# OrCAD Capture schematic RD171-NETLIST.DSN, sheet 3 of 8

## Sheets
3 6: size A3
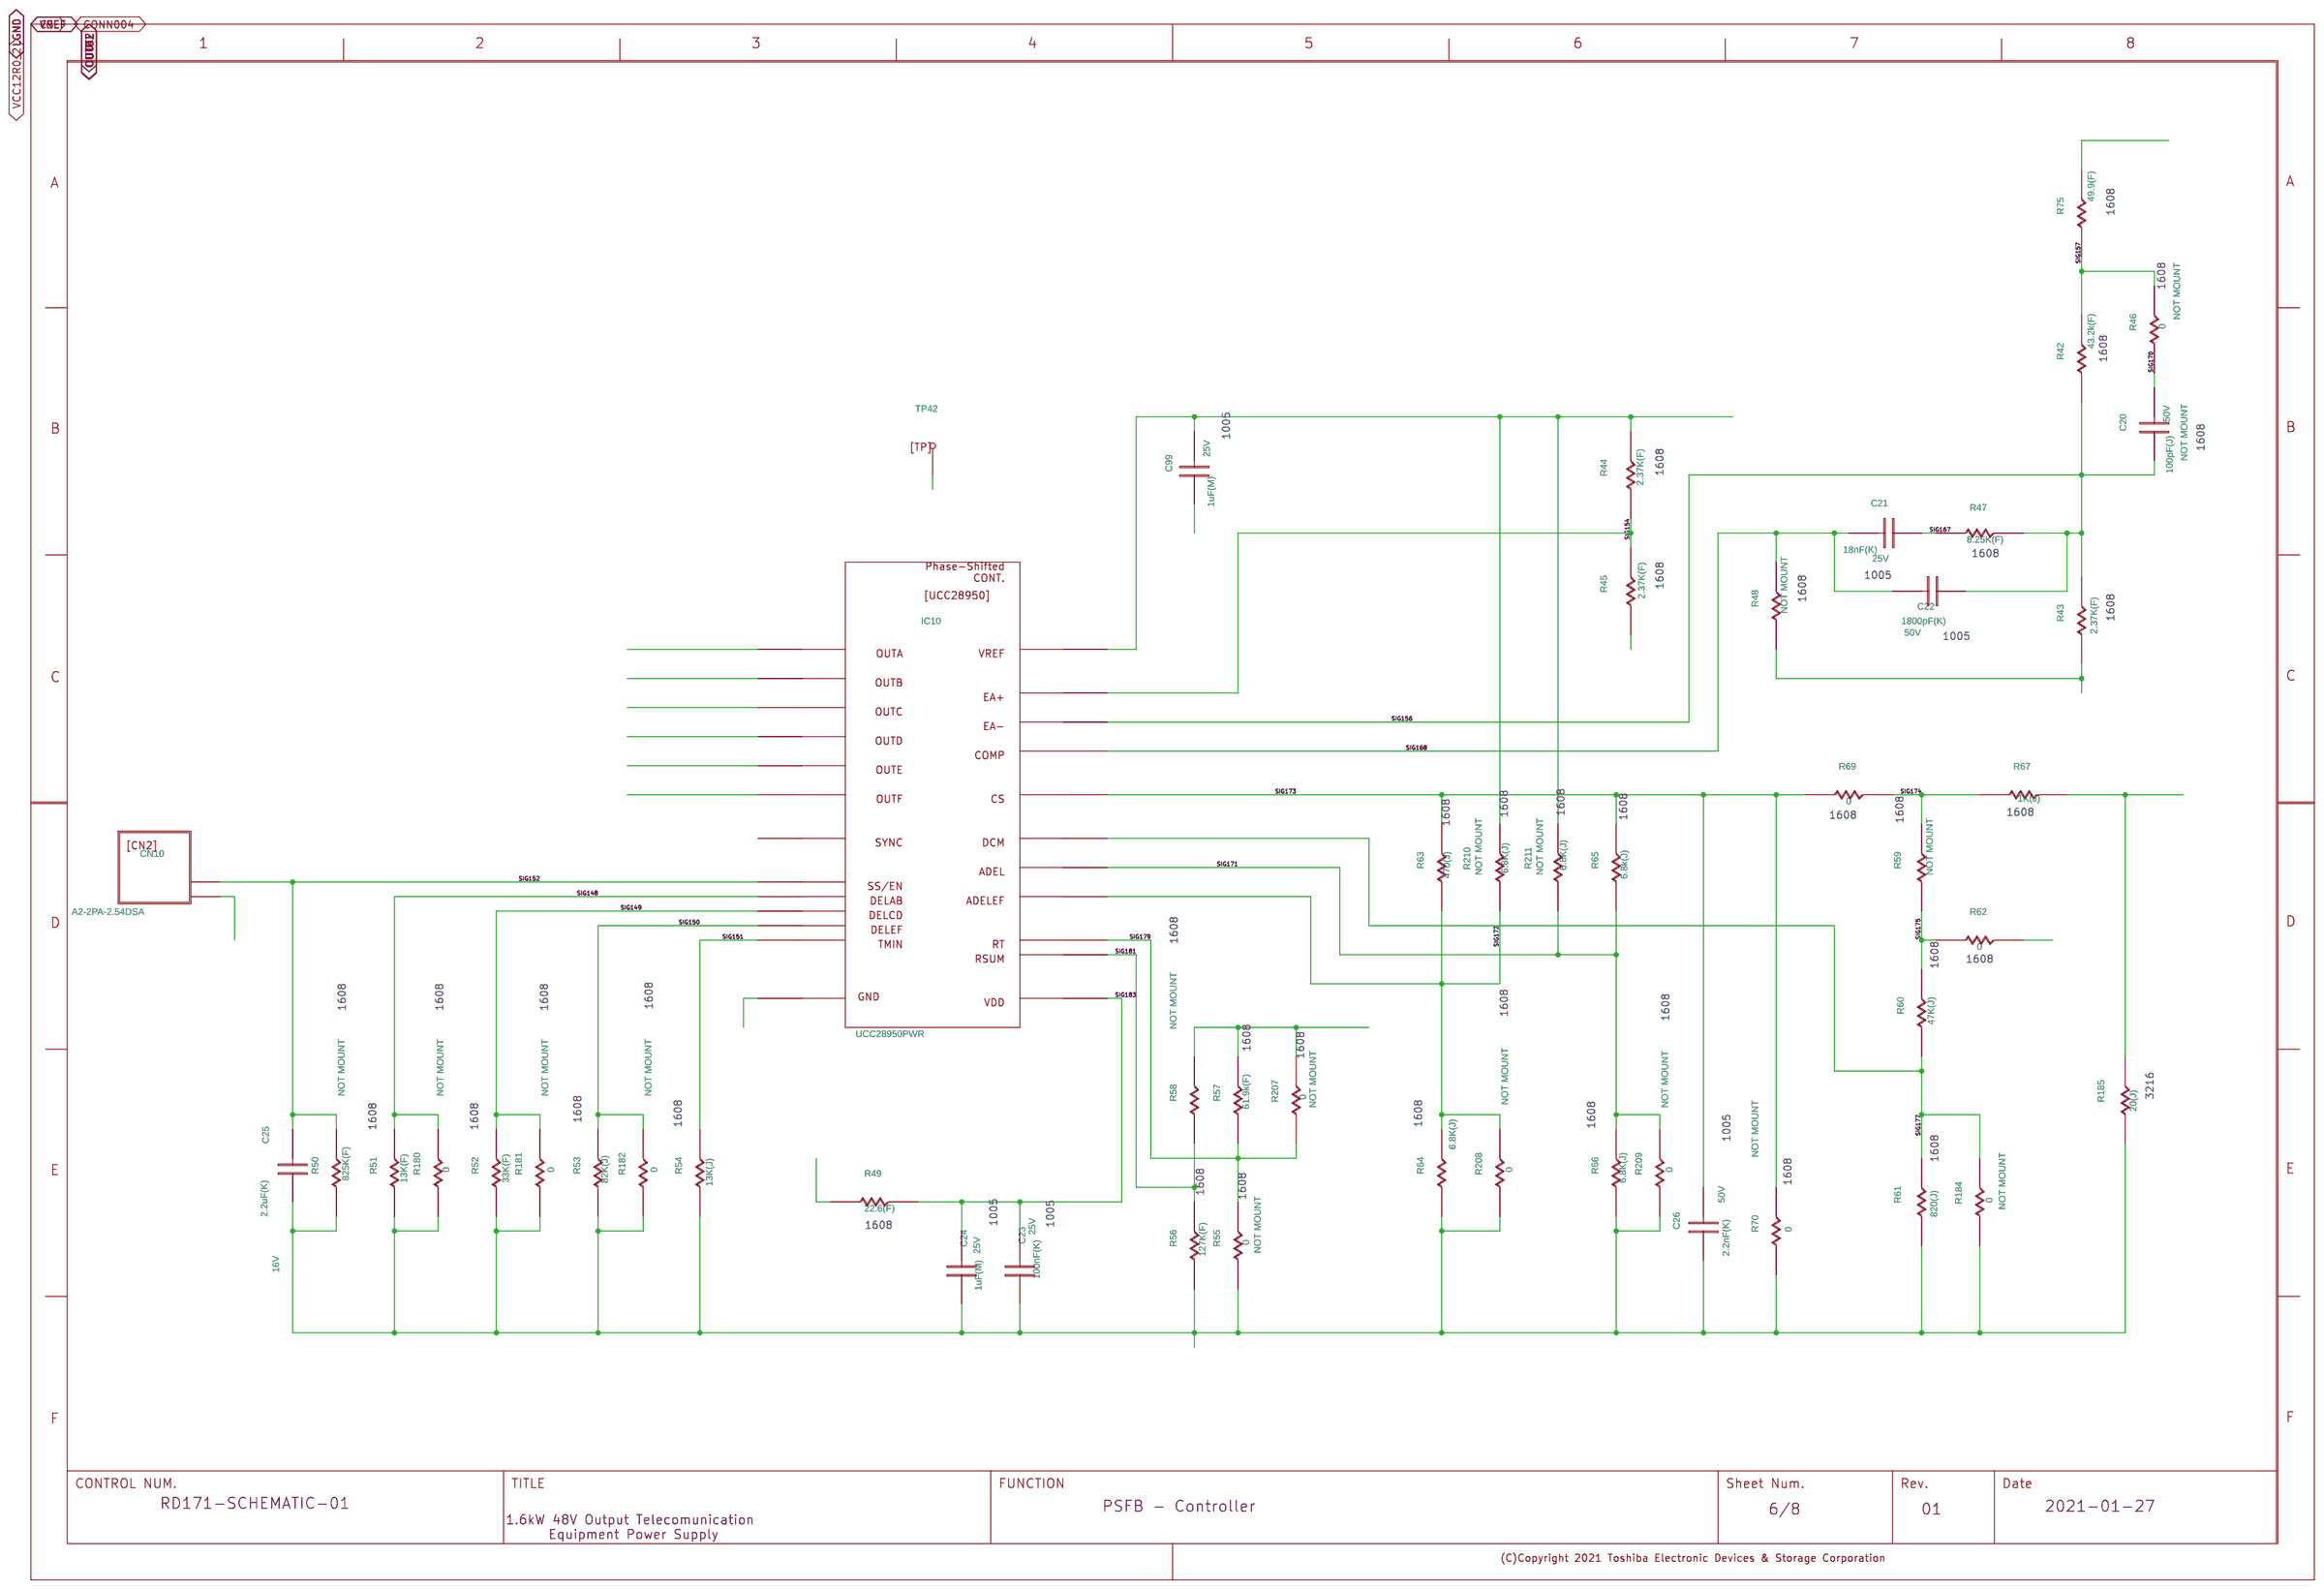
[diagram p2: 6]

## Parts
C20  100pF
C21  18nF
C22  1800pF
C23  100nF
C24  1uF
C25  2.2uF
C26  2.2nF
C99  1uF
CN10  CN10  [A2-2PA-2.54DSA]
IC10  IC10  [UCC28950PWR]
R42  43.2k  [RN73H1JTTD4322F25]
R43  2.37k
R44  2.37k
R45  2.37k
R46  0
R47  8.25k
R48  0
R49  22.6
R50  825k
R51  13k
R52  33k
R53  100k
R54  13k
R55  0
R56  127k
R57  61.9k  [RN73H1JTTD6192F50]
R58  0
R59  0
R60  47k
R61  820
R62  0
R63  100
R64  6.8k
R65  6.8k
R66  6.8k
R67  1k
R69  0
R70  0
R75  49.9
R180  0
R181  0
R182  0
R184  0
R185  20
R207  0
R208  0
R209  0
R210  6.8k
R211  6.8k
TP42  TP42  [LC-22-S-BLACK]
U?#2  WAKU_DEF100

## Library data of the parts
C20 = C: ADSMODELNAME: s_GRM188B11E104KA01D; CAPACITANCETOLE: K; CDMASTERCADCELG: KC0008; CHIPSIZE: 1608; COMP: PRT_48; COMPONENTNAME: C_C.Normal_package; FNLEADFREETHET1GT2GMCTH1: 3_1_N; FUNCTION: C_C.Normal_package; GCOUNT: 1; INSTANCENAME: INS8954; MAXGCOUNT: 1; NOMINALCAPACITA: 100n; NOTMOUNT: NOT MOUNT; OUMECLASSIFICATION: ƒZƒ‰ƒ~ƒbƒNƒRƒ“ƒfƒ“ƒT; OUMEMAKER: MRT ºc»ì; OUMEMAKERKATAMEI: GRM188B11E104KA01D; PARTNAME: Chip1608_GS_1; PMPRODUCTSTYPEG: PC1; QUADMODEL: CON_100N; RATEDVOLTAGE: 25; SIZECODESMD: 1608; TEMPCHARACTERI2: B; VAL1: 100pF(J); VAL2: 50V; VAL3: GRM1885C1H101JA01D
C21 = C: ADSCNVFLAG: ON; ADSCOMPONENTNAME: C_1005; ADSMODELNAME: s_GRM155B11E562KA01D; CAPACITANCETOLE: K; CDMASTERCADCELG: KC0005; CHIPSIZE: 1005; COMP: PRT_52; COMPONENTNAME: C_C.Normal_package; FNLEADFREETHET1GT2GMCTH1: 2_0_N; FUNCTION: C_C.Normal_package; GCOUNT: 1; ICX_PART_MODEL: CON_5.6N; INSTANCENAME: INS8656; MAKER: MURATA; MAXGCOUNT: 1; NOMINALCAPACITA: 5.6n; OUMECLASSIFICATION: ƒZƒ‰ƒ~ƒbƒNƒRƒ“ƒfƒ“ƒT; OUMEMAKER: MRT ºc»ì; OUMEMAKERKATAMEI: GRM155B11E562KA01D; PARTNAME: Chip1005_GS_2; PMPRODUCTSTYPEG: HD1; QUADMODEL: CON_5.6N; RATEDVOLTAGE: 25; SIZECODESMD: 1005; SQ_PART_MODEL: CON_5.6N; TEMPCHARACTERI2: B; VAL1: 18nF(K); VAL2: 25V; VAL3: GRM155R71E183KA61D
C22 = C: ADSCNVFLAG: ON; ADSCOMPONENTNAME: C_1005; ADSMODELNAME: s_C1005JB1H561KT; CAPACITANCETOLE: K; CDMASTERCADCELG: KC0005; CHIPSIZE: 1005; COMP: PRT_52; COMPONENTNAME: C_C.Normal_package; FNLEADFREETHET1GT2GMCTH1: 2_0_N; FUNCTION: C_C.Normal_package; GCOUNT: 1; ICX_PART_MODEL: CON_560P; INSTANCENAME: INS8666; MAKER: MURATA; MAXGCOUNT: 1; NOMINALCAPACITA: 560p; OUMECLASSIFICATION: ƒZƒ‰ƒ~ƒbƒNƒRƒ“ƒfƒ“ƒT; OUMEMAKER: TDK ‚s‚c‚j; OUMEMAKERKATAMEI: C1005JB1H561KT; PARTNAME: Chip1005_GS_2; PMPRODUCTSTYPEG: HD1-PC1; QUADMODEL: CON_560P; RATEDVOLTAGE: 50; SIZECODESMD: 1005; SQ_PART_MODEL: CON_560P; TEMPCHARACTERI2: B; VAL1: 1800pF(K); VAL2: 50V; VAL3: GRM155R71H182KA01D
C23 = C: ADSMODELNAME: s_GRM155R71E104KE14D; CAPACITANCETOLE: K; CDMASTERCADCELG: KC0005; CHIPSIZE: 1005; COMP: PRT_52; COMPONENTNAME: C_C.Normal_package; FNLEADFREETHET1GT2GMCTH1: N_N_N; FUNCTION: C_C.Normal_package; GCOUNT: 1; INSTANCENAME: INS8708; MAKER: TDK; MAXGCOUNT: 1; NOMINALCAPACITA: 100n; OUMECLASSIFICATION: ƒZƒ‰ƒ~ƒbƒNƒRƒ“ƒfƒ“ƒT; OUMEMAKER: MRT ºc»ì; OUMEMAKERKATAMEI: GRM155R71E104KE14D; PARTNAME: Chip1005_GS_2; QUADMODEL: CON_100N; RATEDVOLTAGE: 25; SIZECODESMD: 1005; VAL1: 100nF(K); VAL2: 25V; VAL3: C1005X7R1E104K050BB
C24 = C: ADSMODELNAME: s_GRM155B31E105KA12D; CAPACITANCETOLE: K; CDMASTERCADCELG: KC0005; CHIPSIZE: 1005; COMP: PRT_52; COMPONENTNAME: C_C.Normal_package; FNLEADFREETHET1GT2GMCTH1: 3_0_N; FUNCTION: C_C.Normal_package; GCOUNT: 1; INSTANCENAME: INS8718; MAKER: TDK; MAXGCOUNT: 1; NOMINALCAPACITA: 1u; OUMECLASSIFICATION: ƒZƒ‰ƒ~ƒbƒNƒRƒ“ƒfƒ“ƒT; OUMEMAKER: MRT ºc»ì; OUMEMAKERKATAMEI: GRM155B31E105KA12D; PARTNAME: Chip1005_GS_2; PMPRODUCTSTYPEG: HD1; QUADMODEL: CON_1U; RATEDVOLTAGE: 25; SIZECODESMD: 1005; TEMPCHARACTERI2: B; VAL1: 1uF(M); VAL2: 25V; VAL3: C1005X5R1E105M050BC
C25 = C: ADSMODELNAME: s_GRM155C81C225KE11; CAPACITANCETOLE: K; CDMASTERCADCELG: KC0005; CHIPSIZE: 1005; COMP: PRT_52; COMPONENTNAME: C_C.Normal_package; FNLEADFREETHET1GT2GMCTH1: 3_0_N; FUNCTION: C_C.Normal_package; GCOUNT: 1; INSTANCENAME: INS8624; MAKER: MURATA; MAXGCOUNT: 1; NOMINALCAPACITA: 150n; OUMECLASSIFICATION: ƒZƒ‰ƒ~ƒbƒNƒRƒ“ƒfƒ“ƒT; OUMEMAKER: MURATA; OUMEMAKERKATAMEI: GRM155C81C225KE11; PARTNAME: Chip1005_GS_2; PMPRODUCTSTYPEG: HD1; RATEDVOLTAGE: 25; SIZECODESMD: 1005; VAL1: 2.2uF(K); VAL2: 16V; VAL3: GRM155C81C225KE11
C26 = C: ADSMODELNAME: s_UMK105BJ222KV_F; CAPACITANCETOLE: K; CDMASTERCADCELG: KC0005; CHIPSIZE: 1005; COMP: PRT_52; COMPONENTNAME: C_C.Normal_package; FNLEADFREETHET1GT2GMCTH1: 2_0_N; FUNCTION: C_C.Normal_package; GCOUNT: 1; INSTANCENAME: INS8762; MAKER: TDK; MAXGCOUNT: 1; NOMINALCAPACITA: 2.2n; OUMECLASSIFICATION: ƒZƒ‰ƒ~ƒbƒNƒRƒ“ƒfƒ“ƒT; OUMEMAKER: TYD ‘¾—z—U“d; OUMEMAKERKATAMEI: UMK105BJ222KV-F; PARTNAME: Chip1005_GS_2; PMPRODUCTSTYPEG: HD1-PC1; QUADMODEL: CON_2.2N; RATEDVOLTAGE: 50; SIZECODESMD: 1005; TEMPCHARACTERI2: B; VAL1: 2.2nF(K); VAL2: 50V; VAL3: UMK105BJ222KV-F
C99 = C: ADSMODELNAME: s_GRM155B31E105KA12D; CAPACITANCETOLE: K; CDMASTERCADCELG: KC0005; CHIPSIZE: 1005; COMP: PRT_52; COMPONENTNAME: C_C.Normal_package; FNLEADFREETHET1GT2GMCTH1: 3_0_N; FUNCTION: C_C.Normal_package; GCOUNT: 1; INSTANCENAME: INS8728; MAKER: TDK; MAXGCOUNT: 1; NOMINALCAPACITA: 1u; OUMECLASSIFICATION: ƒZƒ‰ƒ~ƒbƒNƒRƒ“ƒfƒ“ƒT; OUMEMAKER: MRT ºc»ì; OUMEMAKERKATAMEI: GRM155B31E105KA12D; PARTNAME: Chip1005_GS_2; PMPRODUCTSTYPEG: HD1; QUADMODEL: CON_1U; RATEDVOLTAGE: 25; SIZECODESMD: 1005; TEMPCHARACTERI2: B; VAL1: 1uF(M); VAL2: 25V; VAL3: C1005X5R1E105M050BC
CN10 = CN2: COMP: PRT_56; COMPONENTNAME: CN2_CN2.Normal_package; FUNCTION: CN2_CN2.Normal_package; INSTANCENAME: INS9156; MAKER: HIROSE; PARTNAME: A2-2PA-2.54DSA_HR
IC10 = L28950: COMP: PRT_16; COMPONENTNAME: L28950_L28950.Normal_package; FUNCTION: L28950_L28950.Normal_package; INSTANCENAME: INS8570; MAKER: TEXAS; PARTNAME: UCC28950PWR_GS_1; SAVECOUNT: 1; UPDATEDATE: 2020/07/08; UPDATETIME: 16:40:04
R42 = R: ADSMODELNAME: s_RN73H1JTTD4322F25; CDMASTERCADCELG: KC0008; CHIPSIZE: 1608; COMP: PRT_8; COMPONENTNAME: R_R.Normal_package; FNLEADFREETHET1GT2GMCTH1: N_N_N; FUNCTION: R_R.Normal_package; GCOUNT: 1; INSTANCENAME: INS8646; MAKER: PANASONIC; MAXGCOUNT: 1; MOUNTINGFORMSMD: SMD; NOMINALRESISTAN: 9.09K; OUMECLASSIFICATION: \ÊÀpÅèïRí; OUMEMAKER: KOA R[A; OUMEMAKERKATAMEI: RN73H1JTTD9091B10; PARTNAME: Chip1608_GS_1; PMPRODUCTSTYPEG: DME; POWERRATING: 100m; QUADMODEL: RES_9.09K; RESISTANCETOLER: B; SIZECODESMD: 1608; VAL1: 43.2k(F); VAL2: 100mW,}1%; VAL3: ERJ-3EKF9091V
R43 = R: ADSMODELNAME: s_ERJ3EKF2201V@@; CDMASTERCADCELG: KC0165; CHIPSIZE: 1608; COMP: PRT_8; COMPONENTNAME: R_R.Normal_package; FNLEADFREETHET1GT2GMCTH1: 3_2_N; FUNCTION: R_R.Normal_package; GCOUNT: 1; INSTANCENAME: INS8966; MAKER: PANASONIC; MAXGCOUNT: 1; MOUNTINGFORMSMD: SMD; NOMINALRESISTAN: 2.2K; OUMECLASSIFICATION: \ÊÀpÅèïRí; OUMEMAKER: NAE pi\jbNGNgjbNfoCX; OUMEMAKERKATAMEI: ERJ3EKF2201V@@; PARTNAME: Chip1608_GS_1; PMPRODUCTSTYPEG: DA; POWERRATING: 100m; QUADMODEL: RES_2.2K; RESISTANCETOLER: F; SIZECODESMD: 1608; VAL1: 2.37K(F); VAL2: 100mW,}1%; VAL3: ERJ-3EKF2371V
R44 = R: ADSMODELNAME: s_ERJ3EKF2201V@@; CDMASTERCADCELG: KC0165; CHIPSIZE: 1608; COMP: PRT_8; COMPONENTNAME: R_R.Normal_package; FNLEADFREETHET1GT2GMCTH1: 3_2_N; FUNCTION: R_R.Normal_package; GCOUNT: 1; INSTANCENAME: INS8878; MAKER: PANASONIC; MAXGCOUNT: 1; MOUNTINGFORMSMD: SMD; NOMINALRESISTAN: 2.2K; OUMECLASSIFICATION: \ÊÀpÅèïRí; OUMEMAKER: NAE pi\jbNGNgjbNfoCX; OUMEMAKERKATAMEI: ERJ3EKF2201V@@; PARTNAME: Chip1608_GS_1; PMPRODUCTSTYPEG: DA; POWERRATING: 100m; QUADMODEL: RES_2.2K; RESISTANCETOLER: F; SIZECODESMD: 1608; VAL1: 2.37K(F); VAL2: 100mW,}1%; VAL3: ERJ-3EKF2371V
R45 = R: ADSMODELNAME: s_ERJ3EKF2201V@@; CDMASTERCADCELG: KC0165; CHIPSIZE: 1608; COMP: PRT_8; COMPONENTNAME: R_R.Normal_package; FNLEADFREETHET1GT2GMCTH1: 3_2_N; FUNCTION: R_R.Normal_package; GCOUNT: 1; INSTANCENAME: INS8868; MAKER: PANASONIC; MAXGCOUNT: 1; MOUNTINGFORMSMD: SMD; NOMINALRESISTAN: 2.2K; OUMECLASSIFICATION: \ÊÀpÅèïRí; OUMEMAKER: NAE pi\jbNGNgjbNfoCX; OUMEMAKERKATAMEI: ERJ3EKF2201V@@; PARTNAME: Chip1608_GS_1; PMPRODUCTSTYPEG: DA; POWERRATING: 100m; QUADMODEL: RES_2.2K; RESISTANCETOLER: F; SIZECODESMD: 1608; VAL1: 2.37K(F); VAL2: 100mW,}1%; VAL3: ERJ-3EKF2371V
R46 = R: ADSMODELNAME: s_RN73H1JTTD9091B10; CDMASTERCADCELG: KC0008; CHIPSIZE: 1608; COMP: PRT_8; COMPONENTNAME: R_R.Normal_package; FNLEADFREETHET1GT2GMCTH1: N_N_N; FUNCTION: R_R.Normal_package; GCOUNT: 1; INSTANCENAME: INS8676; MAKER: KOA; MAXGCOUNT: 1; MOUNTINGFORMSMD: SMD; NOMINALRESISTAN: 9.09K; NOTMOUNT: NOT MOUNT; OUMECLASSIFICATION: \ÊÀpÅèïRí; OUMEMAKER: KOA R[A; OUMEMAKERKATAMEI: RN73H1JTTD9091B10; PARTNAME: Chip1608_GS_1; PMPRODUCTSTYPEG: DME; POWERRATING: 100m; QUADMODEL: RES_9.09K; RESISTANCETOLER: B; SIZECODESMD: 1608; VAL2: 100mW; VAL3: RK73Z1JTTD
R47 = R: ADSMODELNAME: s_ERJ3EKF8251V; CDMASTERCADCELG: KC0167; CHIPSIZE: 1608; COMP: PRT_8; COMPONENTNAME: R_R.Normal_package; FNLEADFREETHET1GT2GMCTH1: N_N_N; FUNCTION: R_R.Normal_package; GCOUNT: 1; INSTANCENAME: INS8996; MAKER: PANASONIC; MAXGCOUNT: 1; MOUNTINGFORMSMD: SMD; NOMINALRESISTAN: 8.25K; OUMECLASSIFICATION: \ÊÀpÅèïRí; OUMEMAKER: NAE pi\jbNGNgjbNfoCX; OUMEMAKERKATAMEI: ERJ3EKF8251V; PARTNAME: Chip1608_GS_1; POWERRATING: 100m; QUADMODEL: RES_8.25K; RESISTANCETOLER: F; SIZECODESMD: 1608; VAL1: 8.25K(F); VAL2: 100mW,}1%; VAL3: ERJ-3EKF8251V
R48 = R: ADSMODELNAME: s_RK73Z1JTTD; CDMASTERCADCELG: KCK0203; CHIPSIZE: 1608; COMP: PRT_8; COMPONENTNAME: R_R.Normal_package; FNLEADFREETHET1GT2GMCTH1: 3_2_N; FUNCTION: R_R.Normal_package; GCOUNT: 1; INSTANCENAME: INS8976; MAKER: KOA; MAXGCOUNT: 1; MOUNTINGFORMSMD: SMD; NOTMOUNT: NOT MOUNT; OUMECLASSIFICATION: \ÊÀpÅèïRí; OUMEMAKER: KOA R[A; OUMEMAKERKATAMEI: RK73Z1JTTD; PARTNAME: Chip1608_GS_1; PMPRODUCTSTYPEG: DME-HD1-PC1; POWERRATING: 100m; QUADMODEL: RES_0; RESISTANCETOLER: X; SIZECODESMD: 1608; VAL2: 100mW; VAL3: RK73Z1JTTD
R49 = R: ADSMODELNAME: s_RK73B1JRTTD220J; CDMASTERCADCELG: KC0008; CHIPSIZE: 1608; COMP: PRT_8; COMPONENTNAME: R_R.Normal_package; FNLEADFREETHET1GT2GMCTH1: N_N_N; FUNCTION: R_R.Normal_package; GCOUNT: 1; INSTANCENAME: INS8858; MAKER: PANASONIC; MAXGCOUNT: 1; MOUNTINGFORMSMD: SMD; NOMINALRESISTAN: 22; OUMECLASSIFICATION: \ÊÀpÅèïRí; OUMEMAKER: KOA R[A; OUMEMAKERKATAMEI: RK73B1JRTTD220J; PARTNAME: Chip1608_GS_1; POWERRATING: 100m; QUADMODEL: RES_22; RESISTANCETOLER: J; SIZECODESMD: 1608; VAL1: 22.6(F); VAL2: 100mW,}1%; VAL3: ERJ-3EKF22R6V
R50 = R: ADSCNVFLAG: ON; ADSCOMPONENTNAME: R_1608; ADSMODELNAME: s_MCR03EZHF8253; CDMASTERCADCELG: DR802R; CHIPSIZE: 1608; COMP: PRT_8; COMPONENTNAME: R_R.Normal_package; FNLEADFREETHET1GT2GMCTH1: 3_1_N; FUNCTION: R_R.Normal_package; GCOUNT: 1; ICX_PART_MODEL: RES_825K; INSTANCENAME: INS8634; MAKER: PANASONIC; MAXGCOUNT: 1; MOUNTINGFORMSMD: SMD; NOMINALRESISTAN: 825K; NOTMOUNT: NOT MOUNT; OUMECLASSIFICATION: \ÊÀpÅèïRí; OUMEMAKER: ROH [; OUMEMAKERKATAMEI: MCR03EZHF8253; PARTNAME: Chip1608_GS_1; POWERRATING: 100m; QUADMODEL: RES_825K; RESISTANCETOLER: F; SIZECODESMD: 1608; SQ_PART_MODEL: RES_825K; VAL1: 825K(F); VAL2: 100mW,}1%; VAL3: ERJ-3EKF8253V
R51 = R: ADSMODELNAME: s_RN73H1JTTD1302B10; CDMASTERCADCELG: KC0008; CHIPSIZE: 1608; COMP: PRT_8; COMPONENTNAME: R_R.Normal_package; FNLEADFREETHET1GT2GMCTH1: N_N_N; FUNCTION: R_R.Normal_package; GCOUNT: 1; INSTANCENAME: INS8782; MAKER: PANASONIC; MAXGCOUNT: 1; MOUNTINGFORMSMD: SMD; NOMINALRESISTAN: 13K; OUMECLASSIFICATION: \ÊÀpÅèïRí; OUMEMAKER: KOA R[A; OUMEMAKERKATAMEI: RN73H1JTTD1302B10; PARTNAME: Chip1608_GS_1; POWERRATING: 100m; QUADMODEL: RES_13K; RESISTANCETOLER: B; SIZECODESMD: 1608; VAL1: 13K(F); VAL2: 100mW,}1%; VAL3: RK73H1JTTD1302F
R52 = R: ADSMODELNAME: s_RN73H1JTTD3302B10; CDMASTERCADCELG: KC0008; CHIPSIZE: 1608; COMP: PRT_8; COMPONENTNAME: R_R.Normal_package; FNLEADFREETHET1GT2GMCTH1: N_N_N; FUNCTION: R_R.Normal_package; GCOUNT: 1; INSTANCENAME: INS8792; MAKER: PANASONIC; MAXGCOUNT: 1; MOUNTINGFORMSMD: SMD; NOMINALRESISTAN: 33K; OUMECLASSIFICATION: \ÊÀpÅèïRí; OUMEMAKER: KOA R[A; OUMEMAKERKATAMEI: RN73H1JTTD2202B10; PARTNAME: Chip1608_GS_1; POWERRATING: 100m; QUADMODEL: RES_33K; RESISTANCETOLER: B; SIZECODESMD: 1608; VAL1: 33K(F); VAL2: 100mW,}1%; VAL3: RK73H1JTTD3302F
R53 = R: ADSMODELNAME: s_RK73B1JTTD104G; CDMASTERCADCELG: KC0008; CHIPSIZE: 1608; COMP: PRT_8; COMPONENTNAME: R_R.Normal_package; FNLEADFREETHET1GT2GMCTH1: N_N_N; FUNCTION: R_R.Normal_package; GCOUNT: 1; INSTANCENAME: INS8838; MAKER: KOA; MAXGCOUNT: 1; MOUNTINGFORMSMD: SMD; NOMINALRESISTAN: 100K; OUMECLASSIFICATION: \ÊÀpÅèïRí; OUMEMAKER: KOA R[A; OUMEMAKERKATAMEI: RK73B1JTTD104G; PARTNAME: Chip1608_GS_1; POWERRATING: 100m; QUADMODEL: RES_100K; RESISTANCETOLER: G; SIZECODESMD: 1608; VAL1: 82K(J); VAL2: 100mW,}5%; VAL3: RK73B1JTTD104J
R54 = R: ADSCNVFLAG: ON; ADSCOMPONENTNAME: R_1608; ADSMODELNAME: s_RK73H1JTTD1502F; CDMASTERCADCELG: KCK0203; CHIPSIZE: 1608; COMP: PRT_8; COMPONENTNAME: R_R.Normal_package; FNLEADFREETHET1GT2GMCTH1: 3_2_N; FUNCTION: R_R.Normal_package; GCOUNT: 1; ICX_PART_MODEL: RES_15K; INSTANCENAME: INS8848; MAKER: KOA; MAXGCOUNT: 1; MOUNTINGFORMSMD: SMD; NOMINALRESISTAN: 15K; OUMECLASSIFICATION: \ÊÀpÅèïRí; OUMEMAKER: KOA R[A; OUMEMAKERKATAMEI: RK73H1JTTD1502F; PARTNAME: Chip1608_GS_1; PMPRODUCTSTYPEG: DME; POWERRATING: 100m; QUADMODEL: RES_15K; RESISTANCETOLER: F; SIZECODESMD: 1608; SQ_PART_MODEL: RES_15K; VAL1: 13K(J); VAL2: 100mW,}5%; VAL3: RK73B1JTTD153J
R55 = R: ADSMODELNAME: s_RK73Z1JTTD; CDMASTERCADCELG: KCK0203; CHIPSIZE: 1608; COMP: PRT_8; COMPONENTNAME: R_R.Normal_package; FNLEADFREETHET1GT2GMCTH1: 3_2_N; FUNCTION: R_R.Normal_package; GCOUNT: 1; INSTANCENAME: INS9098; MAKER: KOA; MAXGCOUNT: 1; MOUNTINGFORMSMD: SMD; NOTMOUNT: NOT MOUNT; OUMECLASSIFICATION: \ÊÀpÅèïRí; OUMEMAKER: KOA R[A; OUMEMAKERKATAMEI: RK73Z1JTTD; PARTNAME: Chip1608_GS_1; PMPRODUCTSTYPEG: DME-HD1-PC1; POWERRATING: 100m; QUADMODEL: RES_0; RESISTANCETOLER: X; SIZECODESMD: 1608; VAL2: 100mW; VAL3: RK73Z1JTTD
R56 = R: ADSMODELNAME: s_ERJ3EKF1203V; CDMASTERCADCELG: KC0008; CHIPSIZE: 1608; COMP: PRT_8; COMPONENTNAME: R_R.Normal_package; FNLEADFREETHET1GT2GMCTH1: N_N_N; FUNCTION: R_R.Normal_package; GCOUNT: 1; INSTANCENAME: INS9088; MAKER: PANASONIC; MAXGCOUNT: 1; MOUNTINGFORMSMD: SMD; NOMINALRESISTAN: 120K; OUMECLASSIFICATION: \ÊÀpÅèïRí; OUMEMAKER: NAE pi\jbNGNgjbNfoCX; OUMEMAKERKATAMEI: ERJ3EKF1203V; PARTNAME: Chip1608_GS_1; POWERRATING: 100m; QUADMODEL: RES_120K; RESISTANCETOLER: F; SIZECODESMD: 1608; VAL1: 127K(F); VAL2: 100mW,}1%; VAL3: ERJ-3EKF1273V
R57 = R: ADSMODELNAME: s_ERJ3GEYJ104V; CDMASTERCADCELG: DR802R; CHIPSIZE: 1608; COMP: PRT_8; COMPONENTNAME: R_R.Normal_package; FNLEADFREETHET1GT2GMCTH1: 3_1_N; FUNCTION: R_R.Normal_package; GCOUNT: 1; INSTANCENAME: INS8772; MAKER: PANASONIC; MAXGCOUNT: 1; MOUNTINGFORMSMD: SMD; NOMINALRESISTAN: 100K; OUMECLASSIFICATION: \ÊÀpÅèïRí; OUMEMAKER: NAE pi\jbNGNgjbNfoCX; OUMEMAKERKATAMEI: ERJ3GEYJ104V; PARTNAME: Chip1608_GS_1; POWERRATING: 63m; QUADMODEL: RES_100K; RESISTANCETOLER: J; SIZECODESMD: 1608; VAL1: 61.9k(F); VAL2: 100mW,}1%; VAL3: ERJ-3EKF1003V
R58 = R: ADSMODELNAME: s_RK73Z1JTTD; CDMASTERCADCELG: KCK0203; CHIPSIZE: 1608; COMP: PRT_8; COMPONENTNAME: R_R.Normal_package; FNLEADFREETHET1GT2GMCTH1: 3_2_N; FUNCTION: R_R.Normal_package; GCOUNT: 1; INSTANCENAME: INS9078; MAKER: KOA; MAXGCOUNT: 1; MOUNTINGFORMSMD: SMD; NOTMOUNT: NOT MOUNT; OUMECLASSIFICATION: \ÊÀpÅèïRí; OUMEMAKER: KOA R[A; OUMEMAKERKATAMEI: RK73Z1JTTD; PARTNAME: Chip1608_GS_1; PMPRODUCTSTYPEG: DME-HD1-PC1; POWERRATING: 100m; QUADMODEL: RES_0; RESISTANCETOLER: X; SIZECODESMD: 1608; VAL2: 100mW; VAL3: RK73Z1JTTD
R59 = R: ADSMODELNAME: s_RK73Z1JTTD; CDMASTERCADCELG: KCK0203; CHIPSIZE: 1608; COMP: PRT_8; COMPONENTNAME: R_R.Normal_package; FNLEADFREETHET1GT2GMCTH1: 3_2_N; FUNCTION: R_R.Normal_package; GCOUNT: 1; INSTANCENAME: INS9006; MAKER: KOA; MAXGCOUNT: 1; MOUNTINGFORMSMD: SMD; NOTMOUNT: NOT MOUNT; OUMECLASSIFICATION: \ÊÀpÅèïRí; OUMEMAKER: KOA R[A; OUMEMAKERKATAMEI: RK73Z1JTTD; PARTNAME: Chip1608_GS_1; PMPRODUCTSTYPEG: DME-HD1-PC1; POWERRATING: 100m; QUADMODEL: RES_0; RESISTANCETOLER: X; SIZECODESMD: 1608; VAL2: 100mW; VAL3: RK73Z1JTTD
R60 = R: ADSMODELNAME: s_RK73B1JTTD473G; CDMASTERCADCELG: KC0008; CHIPSIZE: 1608; COMP: PRT_8; COMPONENTNAME: R_R.Normal_package; FNLEADFREETHET1GT2GMCTH1: N_N_N; FUNCTION: R_R.Normal_package; GCOUNT: 1; INSTANCENAME: INS9036; MAKER: KOA; MAXGCOUNT: 1; MOUNTINGFORMSMD: SMD; NOMINALRESISTAN: 47K; OUMECLASSIFICATION: \ÊÀpÅèïRí; OUMEMAKER: KOA R[A; OUMEMAKERKATAMEI: RK73B1JTTD473G; PARTNAME: Chip1608_GS_1; POWERRATING: 100m; QUADMODEL: RES_47K; RESISTANCETOLER: G; SIZECODESMD: 1608; VAL1: 47K(J); VAL2: 100mW,}5%; VAL3: RK73B1JTTD473J
R61 = R: ADSMODELNAME: s_RK73G1JTD821D; CDMASTERCADCELG: DR802R; CHIPSIZE: 1608; COMP: PRT_8; COMPONENTNAME: R_R.Normal_package; FNLEADFREETHET1GT2GMCTH1: 3_1_N; FUNCTION: R_R.Normal_package; GCOUNT: 1; INSTANCENAME: INS9046; MAKER: KOA; MAXGCOUNT: 1; MOUNTINGFORMSMD: SMD; OUMECLASSIFICATION: \ÊÀpÅèïRí; OUMEMAKER: KOA R[A; OUMEMAKERKATAMEI: RK73G1JTD821D; PARTNAME: Chip1608_GS_1; POWERRATING: 63m; QUADMODEL: RES_820; RESISTANCETOLER: D; SIZECODESMD: 1608; VAL1: 820(J); VAL2: 125mW,}5%; VAL3: RK73B1JTTD821J
R62 = R: ADSMODELNAME: s_RK73Z1JTTD; CDMASTERCADCELG: KCK0203; CHIPSIZE: 1608; COMP: PRT_8; COMPONENTNAME: R_R.Normal_package; FNLEADFREETHET1GT2GMCTH1: 3_2_N; FUNCTION: R_R.Normal_package; GCOUNT: 1; INSTANCENAME: INS9016; MAKER: KOA; MAXGCOUNT: 1; MOUNTINGFORMSMD: SMD; OUMECLASSIFICATION: \ÊÀpÅèïRí; OUMEMAKER: KOA R[A; OUMEMAKERKATAMEI: RK73Z1JTTD; PARTNAME: Chip1608_GS_1; PMPRODUCTSTYPEG: DME-HD1-PC1; POWERRATING: 100m; QUADMODEL: RES_0; RESISTANCETOLER: X; SIZECODESMD: 1608; VAL2: 100mW; VAL3: RK73Z1JTTD
R63 = R: ADSCOMPONENTNAME: R_1005; ADSMODELNAME: s_CR10_000V; CHIPSIZE: 1608; COMP: PRT_8; COMPONENTNAME: R_R.Normal_package; FUNCTION: R_R.Normal_package; GCOUNT: 1; INSTANCENAME: INS8688; MAKER: KOA; MAXGCOUNT: 1; MOUNTINGFORMSMD: SMD; PARTNAME: Chip1608_GS_1; VAL1: 470(J); VAL2: 125mW,}5%; VAL3: RK73B1JTTD101J
R64 = R: ADSMODELNAME: s_RN73H1JTTD6801B10; CDMASTERCADCELG: KCK0203; CHIPSIZE: 1608; COMP: PRT_8; COMPONENTNAME: R_R.Normal_package; FNLEADFREETHET1GT2GMCTH1: N_N_N; FUNCTION: R_R.Normal_package; GCOUNT: 1; INSTANCENAME: INS8888; MAKER: KOA; MAXGCOUNT: 1; MOUNTINGFORMSMD: SMD; NOMINALRESISTAN: 6.8K; OUMECLASSIFICATION: \ÊÀpÅèïRí; OUMEMAKER: KOA R[A; OUMEMAKERKATAMEI: RN73H1JTTD6801B10; PARTNAME: Chip1608_GS_1; PMPRODUCTSTYPEG: DME; POWERRATING: 100m; QUADMODEL: RES_6.8K; RESISTANCETOLER: B; SIZECODESMD: 1608; VAL1: 6.8K(J); VAL2: 100mW,}5%; VAL3: RK73B1JTTD682J
R65 = R: ADSCOMPONENTNAME: R_1005; ADSMODELNAME: s_CR10_000V; CHIPSIZE: 1608; COMP: PRT_8; COMPONENTNAME: R_R.Normal_package; FUNCTION: R_R.Normal_package; GCOUNT: 1; INSTANCENAME: INS8698; MAKER: KOA; MAXGCOUNT: 1; MOUNTINGFORMSMD: SMD; PARTNAME: Chip1608_GS_1; VAL1: 6.8k(J); VAL2: 100mW,}5%; VAL3: RK73B1JTTD682J
R66 = R: ADSMODELNAME: s_RN73H1JTTD6801B10; CDMASTERCADCELG: KCK0203; CHIPSIZE: 1608; COMP: PRT_8; COMPONENTNAME: R_R.Normal_package; FNLEADFREETHET1GT2GMCTH1: N_N_N; FUNCTION: R_R.Normal_package; GCOUNT: 1; INSTANCENAME: INS8898; MAKER: KOA; MAXGCOUNT: 1; MOUNTINGFORMSMD: SMD; NOMINALRESISTAN: 6.8K; OUMECLASSIFICATION: \ÊÀpÅèïRí; OUMEMAKER: KOA R[A; OUMEMAKERKATAMEI: RN73H1JTTD6801B10; PARTNAME: Chip1608_GS_1; PMPRODUCTSTYPEG: DME; POWERRATING: 100m; QUADMODEL: RES_6.8K; RESISTANCETOLER: B; SIZECODESMD: 1608; VAL1: 6.8K(J); VAL2: 100mW,}5%; VAL3: RK73B1JTTD682J
R67 = R: ADSMODELNAME: s_RN73H1JTTD1001B10; CDMASTERCADCELG: KC0008; CHIPSIZE: 1608; COMP: PRT_8; COMPONENTNAME: R_R.Normal_package; FNLEADFREETHET1GT2GMCTH1: N_N_N; FUNCTION: R_R.Normal_package; GCOUNT: 1; INSTANCENAME: INS9026; MAKER: KOA; MAXGCOUNT: 1; MOUNTINGFORMSMD: SMD; NOMINALRESISTAN: 1K; OUMECLASSIFICATION: \ÊÀpÅèïRí; OUMEMAKER: KOA R[A; OUMEMAKERKATAMEI: RN73H1JTTD1001B10; PARTNAME: Chip1608_GS_1; POWERRATING: 100m; QUADMODEL: RES_1K; RESISTANCETOLER: B; SIZECODESMD: 1608; VAL1: 1K(J); VAL2: 125mW,}5%; VAL3: RK73B1JTTD102J
R69 = R: ADSCNVFLAG: ON; ADSCOMPONENTNAME: R_1608; ADSMODELNAME: s_RK73Z1JTTD; CDMASTERCADCELG: KCK0203; CHIPSIZE: 1608; COMP: PRT_8; COMPONENTNAME: R_R.Normal_package; FNLEADFREETHET1GT2GMCTH1: 3_2_N; FUNCTION: R_R.Normal_package; GCOUNT: 1; ICX_PART_MODEL: RES_0; INSTANCENAME: INS8986; MAKER: KOA; MAXGCOUNT: 1; MOUNTINGFORMSMD: SMD; OUMECLASSIFICATION: \ÊÀpÅèïRí; OUMEMAKER: KOA R[A; OUMEMAKERKATAMEI: RK73Z1JTTD; PARTNAME: Chip1608_GS_1; PMPRODUCTSTYPEG: DME-HD1-PC1; POWERRATING: 100m; QUADMODEL: RES_0; RESISTANCETOLER: X; SIZECODESMD: 1608; SQ_PART_MODEL: RES_0; VAL2: 100mW; VAL3: RK73Z1JTTD
R70 = R: ADSMODELNAME: s_RK73Z1JTTD; CDMASTERCADCELG: KCK0203; CHIPSIZE: 1608; COMP: PRT_8; COMPONENTNAME: R_R.Normal_package; FNLEADFREETHET1GT2GMCTH1: 3_2_N; FUNCTION: R_R.Normal_package; GCOUNT: 1; INSTANCENAME: INS8932; MAKER: KOA; MAXGCOUNT: 1; MOUNTINGFORMSMD: SMD; NOTMOUNT: NOT MOUNT; OUMECLASSIFICATION: \ÊÀpÅèïRí; OUMEMAKER: KOA R[A; OUMEMAKERKATAMEI: RK73Z1JTTD; PARTNAME: Chip1608_GS_1; PMPRODUCTSTYPEG: DME-HD1-PC1; POWERRATING: 100m; QUADMODEL: RES_0; RESISTANCETOLER: X; SIZECODESMD: 1608; VAL2: 100mW; VAL3: RK73Z1JTTD
R75 = R: ADSMODELNAME: s_RK73H1JTTD49R9D@@; CHIPSIZE: 1608; COMP: PRT_8; COMPONENTNAME: R_R.Normal_package; FNLEADFREETHET1GT2GMCTH1: N_N_N; FUNCTION: R_R.Normal_package; GCOUNT: 1; INSTANCENAME: INS8944; MAKER: KOA; MAXGCOUNT: 1; MOUNTINGFORMSMD: SMD; OUMECLASSIFICATION: \ÊÀpÅèïRí; OUMEMAKER: KOA R[A; OUMEMAKERKATAMEI: RK73H1JTTD49R9D@@; PARTNAME: Chip1608_GS_1; POWERRATING: 100m; QUADMODEL: RES_49.9; RESISTANCETOLER: D; SIZECODESMD: 1608; VAL1: 49.9(F); VAL2: 125mW,}1%; VAL3: RK73H1JTTD49R9F
R180 = R: ADSMODELNAME: s_RK73Z1JTTD; CDMASTERCADCELG: KCK0203; CHIPSIZE: 1608; COMP: PRT_8; COMPONENTNAME: R_R.Normal_package; FNLEADFREETHET1GT2GMCTH1: 3_2_N; FUNCTION: R_R.Normal_package; GCOUNT: 1; INSTANCENAME: INS8802; MAKER: KOA; MAXGCOUNT: 1; MOUNTINGFORMSMD: SMD; NOTMOUNT: NOT MOUNT; OUMECLASSIFICATION: \ÊÀpÅèïRí; OUMEMAKER: KOA R[A; OUMEMAKERKATAMEI: RK73Z1JTTD; PARTNAME: Chip1608_GS_1; PMPRODUCTSTYPEG: DME-HD1-PC1; POWERRATING: 100m; QUADMODEL: RES_0; RESISTANCETOLER: X; SIZECODESMD: 1608; VAL2: 100mW; VAL3: RK73Z1JTTD
R181 = R: ADSMODELNAME: s_RK73Z1JTTD; CDMASTERCADCELG: KCK0203; CHIPSIZE: 1608; COMP: PRT_8; COMPONENTNAME: R_R.Normal_package; FNLEADFREETHET1GT2GMCTH1: 3_2_N; FUNCTION: R_R.Normal_package; GCOUNT: 1; INSTANCENAME: INS8814; MAKER: KOA; MAXGCOUNT: 1; MOUNTINGFORMSMD: SMD; NOTMOUNT: NOT MOUNT; OUMECLASSIFICATION: \ÊÀpÅèïRí; OUMEMAKER: KOA R[A; OUMEMAKERKATAMEI: RK73Z1JTTD; PARTNAME: Chip1608_GS_1; PMPRODUCTSTYPEG: DME-HD1-PC1; POWERRATING: 100m; QUADMODEL: RES_0; RESISTANCETOLER: X; SIZECODESMD: 1608; VAL2: 100mW; VAL3: RK73Z1JTTD
R182 = R: ADSMODELNAME: s_RK73Z1JTTD; CDMASTERCADCELG: KCK0203; CHIPSIZE: 1608; COMP: PRT_8; COMPONENTNAME: R_R.Normal_package; FNLEADFREETHET1GT2GMCTH1: 3_2_N; FUNCTION: R_R.Normal_package; GCOUNT: 1; INSTANCENAME: INS8826; MAKER: KOA; MAXGCOUNT: 1; MOUNTINGFORMSMD: SMD; NOTMOUNT: NOT MOUNT; OUMECLASSIFICATION: \ÊÀpÅèïRí; OUMEMAKER: KOA R[A; OUMEMAKERKATAMEI: RK73Z1JTTD; PARTNAME: Chip1608_GS_1; PMPRODUCTSTYPEG: DME-HD1-PC1; POWERRATING: 100m; QUADMODEL: RES_0; RESISTANCETOLER: X; SIZECODESMD: 1608; VAL2: 100mW; VAL3: RK73Z1JTTD
R184 = R: ADSMODELNAME: s_RK73Z1JTTD; CDMASTERCADCELG: KCK0203; CHIPSIZE: 1608; COMP: PRT_8; COMPONENTNAME: R_R.Normal_package; FNLEADFREETHET1GT2GMCTH1: 3_2_N; FUNCTION: R_R.Normal_package; GCOUNT: 1; INSTANCENAME: INS9056; MAKER: KOA; MAXGCOUNT: 1; MOUNTINGFORMSMD: SMD; NOTMOUNT: NOT MOUNT; OUMECLASSIFICATION: \ÊÀpÅèïRí; OUMEMAKER: KOA R[A; OUMEMAKERKATAMEI: RK73Z1JTTD; PARTNAME: Chip1608_GS_1; PMPRODUCTSTYPEG: DME-HD1-PC1; POWERRATING: 100m; QUADMODEL: RES_0; RESISTANCETOLER: X; SIZECODESMD: 1608; VAL2: 100mW; VAL3: RK73Z1JTTD
R185 = R: ADSMODELNAME: s_MCR18EZHJ220; CDMASTERCADCELG: DR901A; CHIPSIZE: 3216; COMP: PRT_5; COMPONENTNAME: R_R.Normal_package; FNLEADFREETHET1GT2GMCTH1: N_N_N; FUNCTION: R_R.Normal_package; GCOUNT: 1; INSTANCENAME: INS9068; MAKER: PANASONIC; MAXGCOUNT: 1; MOUNTINGFORMSMD: SMD; NOMINALRESISTAN: 22; OUMECLASSIFICATION: \ÊÀpÅèïRí; OUMEMAKER: ROH [; OUMEMAKERKATAMEI: MCR18EZHJ220; PARTNAME: Chip3216_GS_1; POWERRATING: 250m; QUADMODEL: RES_22; RESISTANCETOLER: J; SIZECODESMD: 3216; VAL1: 20(J); VAL2: 250mW,}5%; VAL3: ERJ-8GEYJ200V
R207 = R: ADSMODELNAME: s_RK73Z1JTTD; CDMASTERCADCELG: KCK0203; CHIPSIZE: 1608; COMP: PRT_8; COMPONENTNAME: R_R.Normal_package; FNLEADFREETHET1GT2GMCTH1: 3_2_N; FUNCTION: R_R.Normal_package; GCOUNT: 1; INSTANCENAME: INS9110; MAKER: KOA; MAXGCOUNT: 1; MOUNTINGFORMSMD: SMD; NOTMOUNT: NOT MOUNT; OUMECLASSIFICATION: \ÊÀpÅèïRí; OUMEMAKER: KOA R[A; OUMEMAKERKATAMEI: RK73Z1JTTD; PARTNAME: Chip1608_GS_1; PMPRODUCTSTYPEG: DME-HD1-PC1; POWERRATING: 100m; QUADMODEL: RES_0; RESISTANCETOLER: X; SIZECODESMD: 1608; VAL2: 100mW; VAL3: RK73Z1JTTD
R208 = R: ADSMODELNAME: s_RK73Z1JTTD; CDMASTERCADCELG: KCK0203; CHIPSIZE: 1608; COMP: PRT_8; COMPONENTNAME: R_R.Normal_package; FNLEADFREETHET1GT2GMCTH1: 3_2_N; FUNCTION: R_R.Normal_package; GCOUNT: 1; INSTANCENAME: INS8920; MAKER: KOA; MAXGCOUNT: 1; MOUNTINGFORMSMD: SMD; NOTMOUNT: NOT MOUNT; OUMECLASSIFICATION: \ÊÀpÅèïRí; OUMEMAKER: KOA R[A; OUMEMAKERKATAMEI: RK73Z1JTTD; PARTNAME: Chip1608_GS_1; PMPRODUCTSTYPEG: DME-HD1-PC1; POWERRATING: 100m; QUADMODEL: RES_0; RESISTANCETOLER: X; SIZECODESMD: 1608; VAL2: 100mW; VAL3: RK73Z1JTTD
R209 = R: ADSMODELNAME: s_RK73Z1JTTD; CDMASTERCADCELG: KCK0203; CHIPSIZE: 1608; COMP: PRT_8; COMPONENTNAME: R_R.Normal_package; FNLEADFREETHET1GT2GMCTH1: 3_2_N; FUNCTION: R_R.Normal_package; GCOUNT: 1; INSTANCENAME: INS8908; MAKER: KOA; MAXGCOUNT: 1; MOUNTINGFORMSMD: SMD; NOTMOUNT: NOT MOUNT; OUMECLASSIFICATION: \ÊÀpÅèïRí; OUMEMAKER: KOA R[A; OUMEMAKERKATAMEI: RK73Z1JTTD; PARTNAME: Chip1608_GS_1; PMPRODUCTSTYPEG: DME-HD1-PC1; POWERRATING: 100m; QUADMODEL: RES_0; RESISTANCETOLER: X; SIZECODESMD: 1608; VAL2: 100mW; VAL3: RK73Z1JTTD
R210 = R: ADSCOMPONENTNAME: R_1005; ADSMODELNAME: s_ERJ2RHD163X; CHIPSIZE: 1608; COMP: PRT_8; COMPONENTNAME: R_R.Normal_package; FUNCTION: R_R.Normal_package; GCOUNT: 1; INSTANCENAME: INS8738; MAXGCOUNT: 1; MOUNTINGFORMSMD: SMD; NOTMOUNT: NOT MOUNT; PARTNAME: Chip1608_GS_1; PMPRODUCTSTYPEG: DME-HD1; VAL1: 6.8K(J); VAL2: 100mW,}5%; VAL3: RK73B1JTTD682J
R211 = R: ADSCOMPONENTNAME: R_1005; ADSMODELNAME: s_ERJ2RHD163X; CHIPSIZE: 1608; COMP: PRT_8; COMPONENTNAME: R_R.Normal_package; FUNCTION: R_R.Normal_package; GCOUNT: 1; INSTANCENAME: INS8750; MAKER: KOA; MAXGCOUNT: 1; MOUNTINGFORMSMD: SMD; NOTMOUNT: NOT MOUNT; PARTNAME: Chip1608_GS_1; PMPRODUCTSTYPEG: DME-HD1; VAL1: 6.8K(J); VAL2: 100mW,}5%; VAL3: RK73B1JTTD682J
TP42 = TP: COMP: PRT_34; COMPONENTNAME: TP_TP.Normal_package; FUNCTION: TP_TP.Normal_package; ID: LGND; INSTANCENAME: INS9148; MAKER: MAC8; PARTNAME: LC-22_GS
U?#2 = WAKU_DEF100: DATE: 2021-01-27; DRAWINGNUMBER: RD171-SCHEMATIC-01; FUNCTION: PSFB - Controller; REVISION: 01; SAVEAREA0: 168739,-66042,466246,90057; SAVECOUNT: 5; SHEETNUMBER: 6/8; TITLE: 1.6kW 48V Output Telecomunication / Equipment Power Supply; UPDATEDATE: 2021/01/27; UPDATETIME: 15:56:18

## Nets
VCC12R0_2: R49.1 ; also on sheet 1 4
CONN004: R75.2 ; also on sheet 1 4
CS: R67.2 R185.2 ; also on sheet 5
LGND: C23.1 C24.1 C25.1 C26.1 C99.1 CN10.2 IC10.24 R43.1 R45.1 R48.1 R50.1 R51.1 R52.1 R53.1 R54.1 R55.1 R56.1 R61.1 R64.1 R66.1 R70.1 R180.1 R181.1 R182.1 R184.1 R185.1 R208.1 R209.1 TP42.1 ; also on sheet 1 2 4 5 8
OUTA2: IC10.22 ; also on sheet 2
OUTB2: IC10.21 ; also on sheet 2
OUTC2: IC10.20 ; also on sheet 2
OUTD2: IC10.19 ; also on sheet 2
OUTE: IC10.18 ; also on sheet 4
OUTF: IC10.17 ; also on sheet 4
SIG148: IC10.6 R51.2 R180.2
SIG149: IC10.7 R52.2 R181.2
SIG150: IC10.8 R53.2 R182.2
SIG151: IC10.9 R54.2
SIG152: C25.2 CN10.1 IC10.5 R50.2
SIG154: IC10.2 R44.1 R45.2
SIG156: C20.1 C22.1 IC10.3 R42.1 R43.2 R47.2
SIG157: R42.2 R46.2 R75.1
SIG167: C21.1 R47.1
SIG168: C21.2 C22.2 IC10.4 R48.2
SIG170: C20.2 R46.1
SIG171: IC10.14 R65.1 R66.2 R209.2 R211.1
SIG172: IC10.13 R63.1 R64.2 R208.2 R210.1
SIG173: C26.2 IC10.15 R63.2 R65.2 R69.1 R70.2
SIG174: R59.2 R67.1 R69.2
SIG175: R59.1 R60.2 R62.1
SIG177: IC10.12 R60.1 R61.2 R184.2
SIG179: IC10.10 R55.2 R57.1 R207.1
SIG181: IC10.11 R56.2 R58.1
SIG183: C23.2 C24.2 IC10.23 R49.2
VREF: C99.2 IC10.1 R44.2 R57.2 R58.2 R62.2 R207.2 R210.2 R211.2

Not connected (* = marked no-connect by the designer): IC10 16

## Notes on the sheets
sheet 3
- 1608
- 1608
- 1608
- 1005
- 1608
- 1608
- 1608
- 1005
- 1608
- 1608
- 1005
- 1608
- 1608
- 1608
- 1608
- 1608
- 1608
- 1608
- 1608
- 1608
- 1608
- 1608
- 1608
- 1608
- 1608
- 1608
- 1608
- 1608
- 1608
- 1608
- 3216
- 1608
- 1608
- 1608
- 1608
- 1608
- 1608
- 1005
- 1608
- 1608
- 1608
- 1608
- 1608
- 1005
- 1005
